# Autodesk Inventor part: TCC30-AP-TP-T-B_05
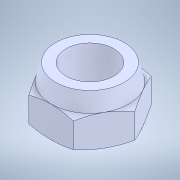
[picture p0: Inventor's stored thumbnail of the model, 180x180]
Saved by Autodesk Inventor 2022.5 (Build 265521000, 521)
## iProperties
Created: 2023-09
Part Number: TCC30-AP-TP-T-B_05
Material: 一般
Document SubType Name: Modeling
Designer: ImaoCorp
Density: 1 g/cm^3
Appearance: 既定
Author: ImaoCorp
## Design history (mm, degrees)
feature "TCC30-AP-TP-T-B_05"
node "ソリッド1"
